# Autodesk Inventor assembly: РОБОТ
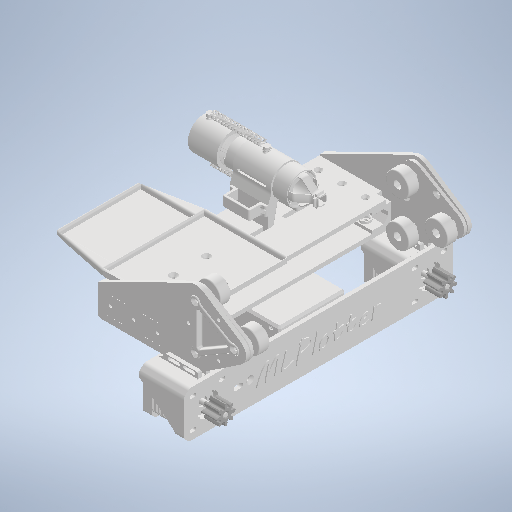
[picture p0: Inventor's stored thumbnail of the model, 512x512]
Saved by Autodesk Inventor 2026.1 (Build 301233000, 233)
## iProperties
Created: 2025-12
Part Number: РОБОТ
Document SubType Name: Assembly
Designer: Yury Melnikov
Author: Yury Melnikov
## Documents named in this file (8)
- C:\Users\user\Documents\Проекты\ВсОШ_РОБО\Робот\РОБОТ.iam
- C:\Users\user\Documents\Проекты\ВсОШ_РОБО\Робот\Направляющие.ipt
- C:\Users\user\Documents\Проекты\ВсОШ_РОБО\Робот\Твердое тело1.ipt
- C:\Users\user\Documents\Проекты\ВсОШ_РОБО\Робот\Твердое тело3.ipt
- C:\Users\user\Documents\Проекты\ВсОШ_РОБО\Робот\Твердое тело4.ipt
- C:\Users\user\Documents\Проекты\ВсОШ_РОБО\Робот\Шестеренки\Шестеренка.ipt
- C:\Users\user\Documents\Проекты\ВсОШ_РОБО\Робот\МАРКЕР.ipt
- C:\Users\user\Documents\Проекты\ВсОШ_РОБО\Робот\аККУМ.ipt
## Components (10 placed, 7 different names)
1. Робот
2. Твердое тело1:1
3. Твердое тело3:1 — Совмещение:1, Совмещение:2, Совмещение:3, Совмещение:4, Угол:1, Совмещение:17, Симметрия:4
4. Твердое тело4:1 — Совмещение:13, Совмещение:14, Совмещение:15, Совмещение:17, Симметрия:2, Совмещение:26
5. Шестеренка:1 — Совмещение:6, Совмещение:7, Совмещение:8, Заподлицо:2
6. Твердое тело1:2
7. Твердое тело3:2 — Совмещение:13, Совмещение:16, Угол:3, Симметрия:4
8. Шестеренка:2 — Совмещение:19, Симметрия:2
9. Маркер — Совмещение:22, Совмещение:23, Совмещение:24
10. Аккумулятор — Совмещение:25, Совмещение:26, Совмещение:27, Угол:6, Совмещение:28, Угол:7
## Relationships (27: Mate 20, Angle 4, Symmetry 2, Flush 1)
- Совмещение:1 [Mate]: Твердое тело3:1
- Совмещение:2 [Mate]: Твердое тело3:1
- Совмещение:3 [Mate]: Твердое тело3:1
- Совмещение:4 [Mate]: Твердое тело3:1
- Угол:1 [Angle]: Твердое тело3:1
- Совмещение:6 [Mate]: Шестеренка:1
- Совмещение:7 [Mate]: Шестеренка:1
- Совмещение:8 [Mate]: Шестеренка:1
- Заподлицо:2 [Flush]: Шестеренка:1
- Совмещение:13 [Mate]: Твердое тело4:1 ↔ Твердое тело3:2
- Совмещение:14 [Mate]: Твердое тело4:1
- Совмещение:15 [Mate]: Твердое тело4:1
- Совмещение:16 [Mate]: Твердое тело3:2
- Совмещение:17 [Mate]: Твердое тело3:1 ↔ Твердое тело4:1
- Угол:3 [Angle]: Твердое тело3:2
- Совмещение:19 [Mate]: Шестеренка:2
- Симметрия:2 [Symmetry]: Твердое тело4:1 ↔ Шестеренка:2
- Совмещение:22 [Mate]: Маркер
- Совмещение:23 [Mate]: Маркер
- Совмещение:24 [Mate]: Маркер
- Совмещение:25 [Mate]: Аккумулятор
- Совмещение:26 [Mate]: Твердое тело4:1 ↔ Аккумулятор
- Совмещение:27 [Mate]: Аккумулятор
- Угол:6 [Angle]: Аккумулятор
- Совмещение:28 [Mate]: Аккумулятор
- Угол:7 [Angle]: Аккумулятор
- Симметрия:4 [Symmetry]: Твердое тело3:1 ↔ Твердое тело3:2
## Named parameters: d14_d2 = 0, d15_d3 = 0, d16_d9 = 0, d17_d13 = 0
